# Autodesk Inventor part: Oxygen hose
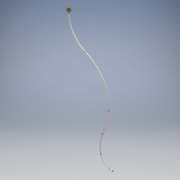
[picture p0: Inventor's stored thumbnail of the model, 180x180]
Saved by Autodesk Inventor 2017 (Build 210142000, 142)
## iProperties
Created: 2020-03
Part Number: Oxygen hose
Material: Generic
Document SubType Name: Modeling
Designer: user
Density: 1 g/cm^3
Appearance: Default
Author: user
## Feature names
1. Sweep1
2. Extrusion1
3. Extrusion2
## Parameters: d5 = 67.98759 mm, d6 = 329.75314 mm, d7 = 19.33825 mm, d8 = 5.10217 mm, d10 = 15 mm, d11 = 607.574 mm, d12 = 6 mm, d13 = 7.25 mm, d14 = 0, d15 = 0, d16 = 12.7 mm, d17 = 21 mm, d18 = 9 mm, d19 = 0, d21 = 0, d22 = 4 mm, d23 = 0
